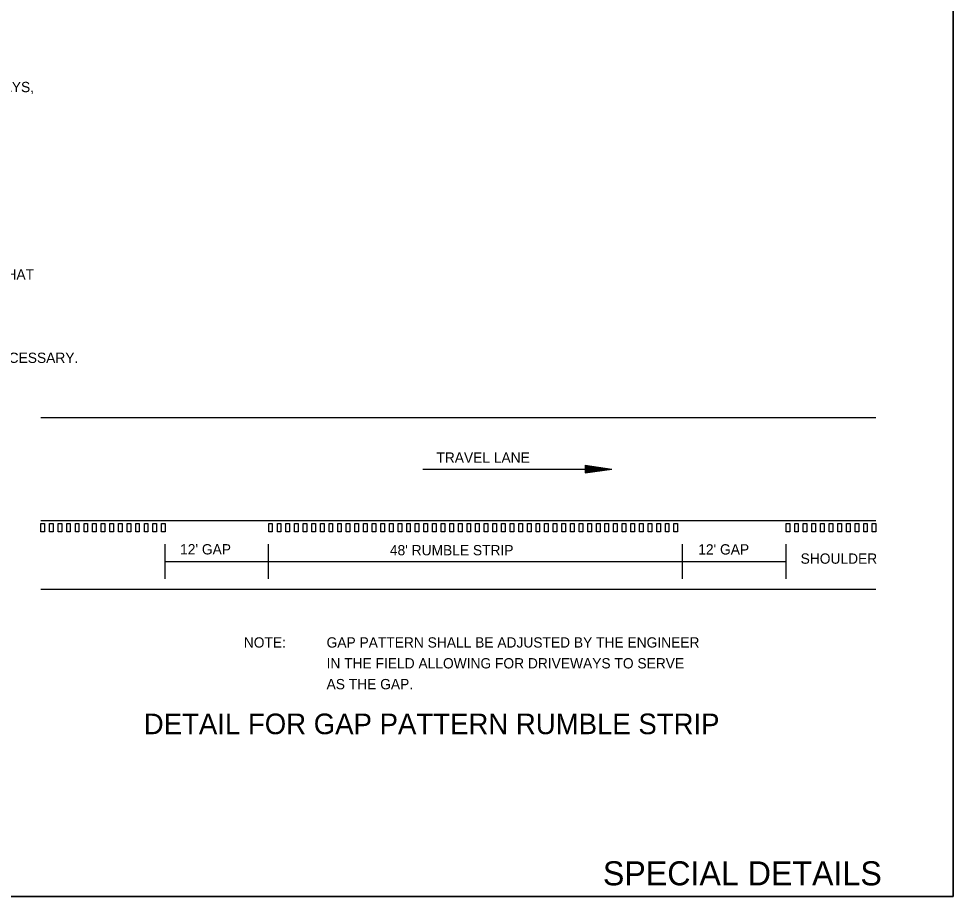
# Model space of a CAD drawing. Extents: x 8229 to 8749, y 14916 to 18021.
# Drawn here: x 8571.4 to 8749, y 15353.5 to 15520.3 of the extents above; entities that cross this region are included whole.
import ezdxf

# ---------------------------------------------------------------- set-up
doc = ezdxf.new("R2010")
doc.units = 0
for name, color, linetype in [('Default', 7, 'Continuous'), ('DSN_DRFT_Junk-No-Plot', 7, 'Continuous'), ('R_Border', 7, 'Continuous'), ('R_Dimension', 7, 'Continuous'), ('R_Draft', 7, 'Continuous')]:
    doc.layers.add(name, color=color, linetype=linetype)

msp = doc.modelspace()

# ---------------------------------------------------------------- linework, layer by layer
at = {"layer": 'Default'}
msp.add_lwpolyline([(8748.98, 15353.52), (8748.98, 15688.81), (8230.82, 15688.81), (8230.82, 15353.52)], close=True, dxfattribs=at)
at = {"layer": 'DSN_DRFT_Junk-No-Plot'}
msp.add_lwpolyline([(8230.82, 15688.81), (8748.98, 15688.81), (8748.98, 15353.52), (8230.82, 15353.52)], close=True, dxfattribs=at)
at = {"layer": 'R_Dimension'}
for p, q in [((8679, 15435.5), (8684.08, 15434.74)), ((8679, 15435.5), (8679, 15433.99)), ((8679, 15435.38), (8683.23, 15434.74)), ((8679, 15435.25), (8682.36, 15434.74)), ((8679, 15435.12), (8681.51, 15434.74)), ((8679, 15434.99), (8680.65, 15434.74)), ((8679, 15434.86), (8679.8, 15434.74)), ((8679, 15433.99), (8684.08, 15434.74)), ((8679, 15434.5), (8680.65, 15434.74)), ((8679, 15434.24), (8682.36, 15434.74)), ((8679, 15434.11), (8683.23, 15434.74)), ((8679, 15434.37), (8681.51, 15434.74)), ((8679, 15434.63), (8679.8, 15434.74))]:
    msp.add_line(p, q, dxfattribs=at)
at = {"layer": 'R_Draft'}
for p, q in [((8575.58, 15444.54), (8734.27, 15444.54)), ((8648.18, 15434.74), (8684.08, 15434.74)), ((8575.58, 15424.95), (8734.27, 15424.95)), ((8599.21, 15413.9), (8599.21, 15420.43)), ((8618.87, 15413.9), (8618.87, 15420.43)), ((8697.54, 15413.9), (8697.54, 15420.43)), ((8717.2, 15413.9), (8717.2, 15420.43)), ((8599.21, 15417.16), (8618.87, 15417.16)), ((8618.87, 15417.16), (8697.54, 15417.16)), ((8697.54, 15417.16), (8717.2, 15417.16)), ((8575.58, 15411.9), (8734.27, 15411.9))]:
    msp.add_line(p, q, dxfattribs=at)
for points in [[(8575.58, 15422.78), (8575.58, 15424.41), (8576.27, 15424.41), (8576.27, 15422.78), (8575.58, 15422.78)], [(8577.22, 15422.78), (8577.22, 15424.41), (8577.9, 15424.41), (8577.9, 15422.78), (8577.22, 15422.78)], [(8578.86, 15422.78), (8578.86, 15424.41), (8579.54, 15424.41), (8579.54, 15422.78), (8578.86, 15422.78)], [(8580.5, 15422.78), (8580.5, 15424.41), (8581.18, 15424.41), (8581.18, 15422.78), (8580.5, 15422.78)], [(8582.14, 15422.78), (8582.14, 15424.41), (8582.82, 15424.41), (8582.82, 15422.78), (8582.14, 15422.78)], [(8583.78, 15422.78), (8583.78, 15424.41), (8584.46, 15424.41), (8584.46, 15422.78), (8583.78, 15422.78)], [(8585.42, 15422.78), (8585.42, 15424.41), (8586.1, 15424.41), (8586.1, 15422.78), (8585.42, 15422.78)], [(8587.05, 15422.78), (8587.05, 15424.41), (8587.74, 15424.41), (8587.74, 15422.78), (8587.05, 15422.78)], [(8588.69, 15422.78), (8588.69, 15424.41), (8589.38, 15424.41), (8589.38, 15422.78), (8588.69, 15422.78)], [(8590.33, 15422.78), (8590.33, 15424.41), (8591.01, 15424.41), (8591.01, 15422.78), (8590.33, 15422.78)], [(8591.97, 15422.78), (8591.97, 15424.41), (8592.65, 15424.41), (8592.65, 15422.78), (8591.97, 15422.78)], [(8593.61, 15422.78), (8593.61, 15424.41), (8594.29, 15424.41), (8594.29, 15422.78), (8593.61, 15422.78)], [(8595.25, 15422.78), (8595.25, 15424.41), (8595.93, 15424.41), (8595.93, 15422.78), (8595.25, 15422.78)], [(8596.89, 15422.78), (8596.89, 15424.41), (8597.57, 15424.41), (8597.57, 15422.78), (8596.89, 15422.78)], [(8598.53, 15422.78), (8598.53, 15424.41), (8599.21, 15424.41), (8599.21, 15422.78), (8598.53, 15422.78)], [(8618.88, 15422.78), (8618.88, 15424.41), (8619.56, 15424.41), (8619.56, 15422.78), (8618.88, 15422.78)], [(8620.52, 15422.78), (8620.52, 15424.41), (8621.2, 15424.41), (8621.2, 15422.78), (8620.52, 15422.78)], [(8622.16, 15422.78), (8622.16, 15424.41), (8622.84, 15424.41), (8622.84, 15422.78), (8622.16, 15422.78)], [(8623.8, 15422.78), (8623.8, 15424.41), (8624.48, 15424.41), (8624.48, 15422.78), (8623.8, 15422.78)], [(8625.44, 15422.78), (8625.44, 15424.41), (8626.12, 15424.41), (8626.12, 15422.78), (8625.44, 15422.78)], [(8627.07, 15422.78), (8627.07, 15424.41), (8627.76, 15424.41), (8627.76, 15422.78), (8627.07, 15422.78)], [(8628.71, 15422.78), (8628.71, 15424.41), (8629.4, 15424.41), (8629.4, 15422.78), (8628.71, 15422.78)], [(8630.35, 15422.78), (8630.35, 15424.41), (8631.03, 15424.41), (8631.03, 15422.78), (8630.35, 15422.78)], [(8631.99, 15422.78), (8631.99, 15424.41), (8632.67, 15424.41), (8632.67, 15422.78), (8631.99, 15422.78)], [(8633.63, 15422.78), (8633.63, 15424.41), (8634.31, 15424.41), (8634.31, 15422.78), (8633.63, 15422.78)], [(8635.27, 15422.78), (8635.27, 15424.41), (8635.95, 15424.41), (8635.95, 15422.78), (8635.27, 15422.78)], [(8636.91, 15422.78), (8636.91, 15424.41), (8637.59, 15424.41), (8637.59, 15422.78), (8636.91, 15422.78)], [(8638.55, 15422.78), (8638.55, 15424.41), (8639.23, 15424.41), (8639.23, 15422.78), (8638.55, 15422.78)], [(8640.18, 15422.78), (8640.18, 15424.41), (8640.87, 15424.41), (8640.87, 15422.78), (8640.18, 15422.78)], [(8641.82, 15422.78), (8641.82, 15424.41), (8642.51, 15424.41), (8642.51, 15422.78), (8641.82, 15422.78)], [(8643.46, 15422.78), (8643.46, 15424.41), (8644.15, 15424.41), (8644.15, 15422.78), (8643.46, 15422.78)], [(8645.1, 15422.78), (8645.1, 15424.41), (8645.78, 15424.41), (8645.78, 15422.78), (8645.1, 15422.78)], [(8646.74, 15422.78), (8646.74, 15424.41), (8647.42, 15424.41), (8647.42, 15422.78), (8646.74, 15422.78)], [(8648.38, 15422.78), (8648.38, 15424.41), (8649.06, 15424.41), (8649.06, 15422.78), (8648.38, 15422.78)], [(8650.02, 15422.78), (8650.02, 15424.41), (8650.7, 15424.41), (8650.7, 15422.78), (8650.02, 15422.78)], [(8651.66, 15422.78), (8651.66, 15424.41), (8652.34, 15424.41), (8652.34, 15422.78), (8651.66, 15422.78)], [(8653.3, 15422.78), (8653.3, 15424.41), (8653.98, 15424.41), (8653.98, 15422.78), (8653.3, 15422.78)], [(8654.93, 15422.78), (8654.93, 15424.41), (8655.62, 15424.41), (8655.62, 15422.78), (8654.93, 15422.78)], [(8656.57, 15422.78), (8656.57, 15424.41), (8657.26, 15424.41), (8657.26, 15422.78), (8656.57, 15422.78)], [(8658.21, 15422.78), (8658.21, 15424.41), (8658.89, 15424.41), (8658.89, 15422.78), (8658.21, 15422.78)], [(8659.85, 15422.78), (8659.85, 15424.41), (8660.53, 15424.41), (8660.53, 15422.78), (8659.85, 15422.78)], [(8661.49, 15422.78), (8661.49, 15424.41), (8662.17, 15424.41), (8662.17, 15422.78), (8661.49, 15422.78)], [(8663.13, 15422.78), (8663.13, 15424.41), (8663.81, 15424.41), (8663.81, 15422.78), (8663.13, 15422.78)], [(8664.77, 15422.78), (8664.77, 15424.41), (8665.45, 15424.41), (8665.45, 15422.78), (8664.77, 15422.78)], [(8666.41, 15422.78), (8666.41, 15424.41), (8667.09, 15424.41), (8667.09, 15422.78), (8666.41, 15422.78)], [(8668.04, 15422.78), (8668.04, 15424.41), (8668.73, 15424.41), (8668.73, 15422.78), (8668.04, 15422.78)], [(8669.68, 15422.78), (8669.68, 15424.41), (8670.37, 15424.41), (8670.37, 15422.78), (8669.68, 15422.78)], [(8671.32, 15422.78), (8671.32, 15424.41), (8672.01, 15424.41), (8672.01, 15422.78), (8671.32, 15422.78)], [(8672.96, 15422.78), (8672.96, 15424.41), (8673.64, 15424.41), (8673.64, 15422.78), (8672.96, 15422.78)], [(8674.6, 15422.78), (8674.6, 15424.41), (8675.28, 15424.41), (8675.28, 15422.78), (8674.6, 15422.78)], [(8676.24, 15422.78), (8676.24, 15424.41), (8676.92, 15424.41), (8676.92, 15422.78), (8676.24, 15422.78)], [(8677.88, 15422.78), (8677.88, 15424.41), (8678.56, 15424.41), (8678.56, 15422.78), (8677.88, 15422.78)], [(8679.52, 15422.78), (8679.52, 15424.41), (8680.2, 15424.41), (8680.2, 15422.78), (8679.52, 15422.78)], [(8681.16, 15422.78), (8681.16, 15424.41), (8681.84, 15424.41), (8681.84, 15422.78), (8681.16, 15422.78)], [(8682.79, 15422.78), (8682.79, 15424.41), (8683.48, 15424.41), (8683.48, 15422.78), (8682.79, 15422.78)], [(8684.43, 15422.78), (8684.43, 15424.41), (8685.12, 15424.41), (8685.12, 15422.78), (8684.43, 15422.78)], [(8686.07, 15422.78), (8686.07, 15424.41), (8686.75, 15424.41), (8686.75, 15422.78), (8686.07, 15422.78)], [(8687.71, 15422.78), (8687.71, 15424.41), (8688.39, 15424.41), (8688.39, 15422.78), (8687.71, 15422.78)], [(8689.35, 15422.78), (8689.35, 15424.41), (8690.03, 15424.41), (8690.03, 15422.78), (8689.35, 15422.78)], [(8690.99, 15422.78), (8690.99, 15424.41), (8691.67, 15424.41), (8691.67, 15422.78), (8690.99, 15422.78)], [(8692.63, 15422.78), (8692.63, 15424.41), (8693.31, 15424.41), (8693.31, 15422.78), (8692.63, 15422.78)], [(8694.27, 15422.78), (8694.27, 15424.41), (8694.95, 15424.41), (8694.95, 15422.78), (8694.27, 15422.78)], [(8695.9, 15422.78), (8695.9, 15424.41), (8696.59, 15424.41), (8696.59, 15422.78), (8695.9, 15422.78)], [(8717.2, 15422.78), (8717.2, 15424.41), (8717.89, 15424.41), (8717.89, 15422.78), (8717.2, 15422.78)], [(8718.84, 15422.78), (8718.84, 15424.41), (8719.53, 15424.41), (8719.53, 15422.78), (8718.84, 15422.78)], [(8720.48, 15422.78), (8720.48, 15424.41), (8721.16, 15424.41), (8721.16, 15422.78), (8720.48, 15422.78)], [(8722.12, 15422.78), (8722.12, 15424.41), (8722.8, 15424.41), (8722.8, 15422.78), (8722.12, 15422.78)], [(8723.76, 15422.78), (8723.76, 15424.41), (8724.44, 15424.41), (8724.44, 15422.78), (8723.76, 15422.78)], [(8725.4, 15422.78), (8725.4, 15424.41), (8726.08, 15424.41), (8726.08, 15422.78), (8725.4, 15422.78)], [(8727.04, 15422.78), (8727.04, 15424.41), (8727.72, 15424.41), (8727.72, 15422.78), (8727.04, 15422.78)], [(8728.68, 15422.78), (8728.68, 15424.41), (8729.36, 15424.41), (8729.36, 15422.78), (8728.68, 15422.78)], [(8730.31, 15422.78), (8730.31, 15424.41), (8731, 15424.41), (8731, 15422.78), (8730.31, 15422.78)], [(8731.95, 15422.78), (8731.95, 15424.41), (8732.64, 15424.41), (8732.64, 15422.78), (8731.95, 15422.78)], [(8733.59, 15422.78), (8733.59, 15424.41), (8734.27, 15424.41), (8734.27, 15422.78), (8733.59, 15422.78)]]:
    msp.add_lwpolyline(points, dxfattribs=at)

# ---------------------------------------------------------------- texts
at = {"layer": 'Default'}
for s, p in [('RUMBLE STRIPS SHALL NOT BE INSTALLED ON CURB SECTIONS, BRIDGE DECKS, APPROACH SLABS, INTERSECTING STREETS OR ROADWAYS,', (8390.07, 15506.38)), ('RUMBLE STRIPS SHALL BE MEASURED BY THE LINEAR FOOT LONGITUDINALLY ALONG THE SHOULDER.  PAYMENT SHALL ONLY INCLUDE THAT', (8390.07, 15470.75)), ('THE 3/8" DEPTH SHALL GENERALLY APPLY FOR THE ENTIRE 12" LENGTH. SOME VARIATION TO SUIT SHOULDER SLOPE BREAKS MAY BE NECESSARY.', (8390.07, 15454.91))]:
    msp.add_text(s, height=1.95822, dxfattribs=at).set_placement(p)
at = {"layer": 'R_Border'}
msp.add_text('SPECIAL DETAILS', height=4.572, dxfattribs=at).set_placement((8682.39, 15355.61))
at = {"layer": 'R_Draft'}
for s, height, p in [('TRAVEL LANE', 1.9582, (8650.75, 15435.95)), ("12' GAP", 1.958, (8602.04, 15418.51)), ("48' RUMBLE STRIP", 1.9582, (8641.91, 15418.34)), ("12' GAP", 1.958, (8700.51, 15418.49)), ('SHOULDER', 1.958, (8719.97, 15416.74)), ('NOTE:', 1.958, (8614.15, 15400.8)), ('GAP PATTERN SHALL BE ADJUSTED BY THE ENGINEER', 1.9582, (8629.88, 15400.8)), ('IN THE FIELD ALLOWING FOR DRIVEWAYS TO SERVE', 1.9582, (8629.88, 15396.84)), ('AS THE GAP.', 1.9582, (8629.88, 15392.88)), ('DETAIL FOR GAP PATTERN RUMBLE STRIP', 3.9164, (8595.14, 15384.34))]:
    msp.add_text(s, height=height, dxfattribs=at).set_placement(p)

doc.saveas('drawing.dxf')
